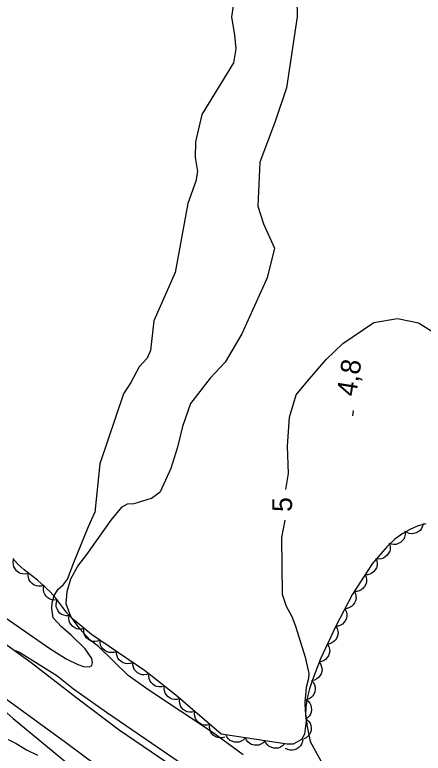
# Model space of a CAD drawing. Extents: x 282461 to 284471, y 5554090 to 5557646.
# Drawn here: x 283492.9 to 283555, y 5555063.9 to 5555176.2 of the extents above; entities that cross this region are included whole.
import ezdxf

# ---------------------------------------------------------------- set-up
doc = ezdxf.new("R2010")
doc.units = 0
for name, color, linetype in [('Niveau 1', 7, 'Continuous'), ('Niveau 2', 7, 'Continuous'), ('Niveau 21', 7, 'Continuous'), ('Niveau 3', 7, 'Continuous'), ('Niveau 44', 7, 'Continuous')]:
    doc.layers.add(name, color=color, linetype=linetype)

msp = doc.modelspace()

# ---------------------------------------------------------------- linework, layer by layer
at = {"layer": 'Niveau 1'}
for points in [[(283535.71, 5555181.58), (283535.78, 5555175.9), (283534.16, 5555165.1), (283532.47, 5555159.98), (283530.1, 5555153.8), (283529.83, 5555147.08), (283530.68, 5555144.42), (283532.35, 5555140.72), (283531.24, 5555136.19), (283527.39, 5555127.68), (283524.88, 5555123.37), (283522.58, 5555120.91), (283519.61, 5555117.05), (283518.37, 5555113.56), (283517.59, 5555110.42), (283516.58, 5555107.17), (283515, 5555103.66)], [(283534.05, 5555103.98), (283534.49, 5555106.41), (283534.33, 5555110.59), (283534.62, 5555115), (283535.63, 5555118.37), (283537.35, 5555120.48), (283540.22, 5555123.75), (283542.75, 5555126.21), (283547.47, 5555129.39), (283551.07, 5555130.01), (283554.22, 5555129.34), (283557.5, 5555127.29)], [(283527.58, 5555063.66), (283523.05, 5555067), (283513.09, 5555073.55), (283510.09, 5555075.7), (283505.62, 5555080.12), (283504.32, 5555081.1), (283502.78, 5555082.81), (283501.4, 5555084.7), (283500.69, 5555086.61), (283500.84, 5555088.48), (283501.38, 5555090.39), (283502.44, 5555092.31), (283503.84, 5555094.12), (283507.51, 5555099.31), (283509.19, 5555101.36), (283510.02, 5555101.82), (283511.03, 5555101.88), (283513.64, 5555102.66), (283515, 5555103.66)], [(283533.92, 5555099.32), (283533.44, 5555096.7), (283533.51, 5555088.08)], [(283533.51, 5555088.08), (283534.15, 5555086.27), (283534.99, 5555084.68), (283535.56, 5555083.19), (283537.02, 5555078.49), (283537.57, 5555075.99), (283537.51, 5555075.26), (283537.17, 5555073.86), (283536.95, 5555071.64), (283537.01, 5555070.29), (283537.31, 5555067.96), (283537.77, 5555065.66), (283539.94, 5555061.71)], [(283479.85, 5555080.49), (283480.04, 5555080), (283481.33, 5555078.62), (283485.67, 5555075.3), (283492.66, 5555069.16), (283500.75, 5555062.46), (283505.49, 5555059.03), (283506.31, 5555058.51), (283512.41, 5555053.82), (283513.23, 5555053.3), (283513.99, 5555052.67), (283517.16, 5555050.38), (283521.9, 5555047.01), (283527.52, 5555043.35), (283532.97, 5555039.58)], [(283550.97, 5555044.85), (283549.76, 5555044.49), (283548.78, 5555044.08), (283547.73, 5555044.13), (283546.28, 5555044.58), (283544.87, 5555045.26), (283541.66, 5555047.08), (283532.05, 5555053.31), (283527.43, 5555056.16), (283518.53, 5555062.05), (283506.82, 5555070.05), (283501.78, 5555073.6), (283499.26, 5555075.66), (283493.58, 5555079.2), (283493.03, 5555079.45)]]:
    msp.add_lwpolyline(points, dxfattribs=at)
at = {"layer": 'Niveau 2'}
for points in [[(283527.26, 5555199.65), (283526.63, 5555197.69), (283526.06, 5555191.79), (283525.15, 5555188.16), (283526.5, 5555180.27), (283525.83, 5555175.9), (283526.27, 5555173.11), (283526.46, 5555171.02), (283526.14, 5555168.87), (283521.3, 5555161.04), (283520.33, 5555156.89), (283520.28, 5555154.51), (283520.64, 5555152.38), (283520.4, 5555150.87), (283519.2, 5555147.47), (283517.27, 5555137.02), (283514.03, 5555129.65), (283513.53, 5555125.12), (283513, 5555123.99), (283511.76, 5555122.66), (283510.51, 5555120.28), (283509.4, 5555118.54), (283505.8, 5555107.91), (283505.07, 5555100.48)], [(283487.73, 5555087.06), (283498.22, 5555079.79), (283500.68, 5555078.25), (283502.44, 5555077.4), (283503.31, 5555077.06), (283504.24, 5555077.01), (283504.59, 5555077.24), (283504.7, 5555077.65), (283504.58, 5555078.29), (283503.57, 5555079.78), (283501.45, 5555081.85), (283499.99, 5555083.11), (283498.69, 5555084.49), (283498.5, 5555085.89), (283498.55, 5555086.76), (283498.88, 5555087.86), (283499.45, 5555088.85), (283500.26, 5555089.56), (283500.91, 5555090.36), (283501.86, 5555092.9), (283504.09, 5555098.34), (283505.07, 5555100.48)], [(283491.87, 5555065.98), (283493.1, 5555065.35), (283494.68, 5555064.38), (283496.32, 5555063.59)]]:
    msp.add_lwpolyline(points, dxfattribs=at)
at = {"layer": 'Niveau 21'}
for points in [[(283413.42, 5555140.21), (283421.33, 5555134.67), (283426.37, 5555130.54), (283431.1, 5555126.98), (283442.51, 5555117.98), (283465.73, 5555100.21), (283486.01, 5555084.44), (283495.36, 5555077.69), (283502.3, 5555072.3), (283508.75, 5555067.43), (283523.36, 5555057.48), (283536.74, 5555048.04), (283543.91, 5555042.83), (283565.1, 5555029.01), (283588.76, 5555014.39), (283602.76, 5555005.89), (283612.36, 5554999.72), (283619.33, 5554995.38), (283626, 5554991.56)], [(283425.48, 5555124.33), (283433.79, 5555117.1), (283443.38, 5555109.82), (283454.24, 5555101.15), (283463.77, 5555093.41), (283469.75, 5555088.42), (283480.65, 5555079.87), (283491.05, 5555072.49), (283500.6, 5555065.57), (283510.11, 5555058.47)]]:
    msp.add_lwpolyline(points, dxfattribs=at)
at = {"layer": 'Niveau 3'}
msp.add_line((283544.25, 5555115.2), (283544.37, 5555115.99), dxfattribs=at)
at = {"layer": 'Niveau 44'}
for points in [[(283554.94, 5555098.82), (283554.86, 5555098.41), (283554.67, 5555098.05), (283554.48, 5555097.78), (283554.2, 5555097.56), (283553.88, 5555097.38), (283553.51, 5555097.29), (283553.18, 5555097.25), (283552.84, 5555097.31), (283552.49, 5555097.43), (283552.18, 5555097.62)], [(283555.34, 5555098.76), (283554.17, 5555098.49), (283553, 5555097.98), (283551.84, 5555097.3), (283550.65, 5555096.43), (283549.46, 5555095.33), (283547.18, 5555092.68), (283544.21, 5555088.06), (283541.67, 5555083.21), (283539.34, 5555078.22), (283538.14, 5555075.06), (283537.67, 5555073.65), (283537.32, 5555072.27), (283537.09, 5555070.92), (283537.06, 5555069.65), (283537.19, 5555068.8), (283536.92, 5555066.78), (283536.47, 5555065.96), (283535.2, 5555065.26), (283534.27, 5555065.25), (283524.27, 5555066.78), (283517.34, 5555072.69), (283514.23, 5555075.22), (283512.61, 5555076.47), (283504.53, 5555081.95), (283501.9, 5555084.13), (283500.78, 5555085.24), (283499.14, 5555087.44), (283498.24, 5555088.44), (283496.34, 5555090.18), (283494.32, 5555091.77), (283493.42, 5555092.61), (283492.59, 5555093.49)], [(283552.2, 5555097.57), (283552.22, 5555097.15), (283552.12, 5555096.75), (283551.99, 5555096.45), (283551.77, 5555096.17), (283551.49, 5555095.93), (283551.15, 5555095.76), (283550.84, 5555095.65), (283550.49, 5555095.63), (283550.12, 5555095.67), (283549.78, 5555095.79)], [(283549.81, 5555095.74), (283549.92, 5555095.34), (283549.91, 5555094.93), (283549.86, 5555094.6), (283549.7, 5555094.29), (283549.49, 5555093.99), (283549.19, 5555093.74), (283548.92, 5555093.56), (283548.58, 5555093.46), (283548.21, 5555093.42), (283547.85, 5555093.46)], [(283494.9, 5555091.22), (283494.5, 5555091.13), (283494.09, 5555091.16), (283493.77, 5555091.23), (283493.46, 5555091.39), (283493.16, 5555091.62), (283492.93, 5555091.93), (283492.76, 5555092.21), (283492.68, 5555092.55), (283492.65, 5555092.92), (283492.71, 5555093.28)], [(283547.74, 5555093.55), (283547.9, 5555093.16), (283547.95, 5555092.76), (283547.94, 5555092.43), (283547.83, 5555092.09), (283547.66, 5555091.77), (283547.4, 5555091.48), (283547.16, 5555091.27), (283546.83, 5555091.12), (283546.47, 5555091.03), (283546.11, 5555091.02)], [(283497.31, 5555089.42), (283496.91, 5555089.29), (283496.5, 5555089.28), (283496.17, 5555089.32), (283495.85, 5555089.46), (283495.54, 5555089.67), (283495.28, 5555089.95), (283495.09, 5555090.21), (283494.98, 5555090.55), (283494.92, 5555090.92), (283494.95, 5555091.28)], [(283546.11, 5555091.02), (283546.28, 5555090.64), (283546.32, 5555090.23), (283546.31, 5555089.9), (283546.21, 5555089.57), (283546.03, 5555089.24), (283545.78, 5555088.95), (283545.53, 5555088.74), (283545.21, 5555088.6), (283544.85, 5555088.5), (283544.49, 5555088.49)], [(283499.35, 5555087.21), (283498.94, 5555087.15), (283498.53, 5555087.21), (283498.22, 5555087.31), (283497.92, 5555087.5), (283497.65, 5555087.75), (283497.45, 5555088.08), (283497.3, 5555088.37), (283497.25, 5555088.72), (283497.25, 5555089.09), (283497.34, 5555089.44)], [(283544.45, 5555088.52), (283544.65, 5555088.15), (283544.73, 5555087.75), (283544.75, 5555087.42), (283544.67, 5555087.08), (283544.53, 5555086.73), (283544.3, 5555086.43), (283544.07, 5555086.19), (283543.76, 5555086.02), (283543.41, 5555085.9), (283543.06, 5555085.85)], [(283501.12, 5555084.78), (283500.71, 5555084.76), (283500.31, 5555084.86), (283500, 5555084.98), (283499.73, 5555085.2), (283499.48, 5555085.48), (283499.31, 5555085.82), (283499.19, 5555086.13), (283499.17, 5555086.48), (283499.21, 5555086.85), (283499.33, 5555087.19)], [(283543.06, 5555085.85), (283543.25, 5555085.49), (283543.33, 5555085.09), (283543.36, 5555084.76), (283543.28, 5555084.41), (283543.13, 5555084.07), (283542.9, 5555083.77), (283542.68, 5555083.53), (283542.37, 5555083.36), (283542.02, 5555083.23), (283541.66, 5555083.19)], [(283503.44, 5555082.85), (283503.04, 5555082.73), (283502.63, 5555082.74), (283502.31, 5555082.79), (283501.99, 5555082.93), (283501.68, 5555083.14), (283501.43, 5555083.44), (283501.25, 5555083.7), (283501.14, 5555084.04), (283501.09, 5555084.41), (283501.13, 5555084.77)], [(283541.66, 5555083.19), (283541.88, 5555082.83), (283541.98, 5555082.44), (283542.01, 5555082.11), (283541.95, 5555081.76), (283541.82, 5555081.42), (283541.6, 5555081.1), (283541.39, 5555080.85), (283541.09, 5555080.67), (283540.75, 5555080.53), (283540.39, 5555080.47)], [(283505.85, 5555081.06), (283505.46, 5555080.9), (283505.05, 5555080.87), (283504.72, 5555080.88), (283504.39, 5555081), (283504.07, 5555081.18), (283503.79, 5555081.44), (283503.58, 5555081.69), (283503.44, 5555082.02), (283503.36, 5555082.38), (283503.36, 5555082.74)], [(283508.33, 5555079.37), (283507.95, 5555079.21), (283507.54, 5555079.18), (283507.21, 5555079.2), (283506.88, 5555079.31), (283506.55, 5555079.49), (283506.28, 5555079.76), (283506.07, 5555080.01), (283505.93, 5555080.33), (283505.85, 5555080.7), (283505.85, 5555081.06)], [(283540.39, 5555080.47), (283540.61, 5555080.11), (283540.7, 5555079.72), (283540.74, 5555079.39), (283540.68, 5555079.04), (283540.55, 5555078.69), (283540.33, 5555078.38), (283540.12, 5555078.13), (283539.82, 5555077.95), (283539.48, 5555077.81), (283539.12, 5555077.75)], [(283510.82, 5555077.68), (283510.43, 5555077.53), (283510.03, 5555077.49), (283509.7, 5555077.51), (283509.36, 5555077.63), (283509.04, 5555077.81), (283508.76, 5555078.07), (283508.55, 5555078.32), (283508.42, 5555078.65), (283508.33, 5555079.01), (283508.33, 5555079.37)], [(283513.31, 5555076), (283512.92, 5555075.84), (283512.51, 5555075.81), (283512.18, 5555075.82), (283511.85, 5555075.94), (283511.53, 5555076.12), (283511.25, 5555076.39), (283511.04, 5555076.63), (283510.9, 5555076.96), (283510.82, 5555077.32), (283510.82, 5555077.68)], [(283539.16, 5555077.73), (283539.4, 5555077.39), (283539.52, 5555077), (283539.58, 5555076.68), (283539.55, 5555076.33), (283539.45, 5555075.97), (283539.25, 5555075.64), (283539.06, 5555075.38), (283538.77, 5555075.17), (283538.44, 5555075.01), (283538.09, 5555074.92)], [(283515.63, 5555074.08), (283515.23, 5555073.96), (283514.82, 5555073.96), (283514.49, 5555074.01), (283514.17, 5555074.15), (283513.86, 5555074.36), (283513.61, 5555074.65), (283513.42, 5555074.92), (283513.32, 5555075.25), (283513.27, 5555075.62), (283513.3, 5555075.98)], [(283517.96, 5555072.19), (283517.56, 5555072.07), (283517.15, 5555072.07), (283516.82, 5555072.11), (283516.5, 5555072.26), (283516.2, 5555072.46), (283515.94, 5555072.75), (283515.75, 5555073.02), (283515.65, 5555073.36), (283515.6, 5555073.72), (283515.63, 5555074.08)], [(283538, 5555074.95), (283538.28, 5555074.64), (283538.45, 5555074.27), (283538.55, 5555073.95), (283538.55, 5555073.6), (283538.49, 5555073.23), (283538.34, 5555072.88), (283538.17, 5555072.6), (283537.91, 5555072.36), (283537.6, 5555072.16), (283537.26, 5555072.04)], [(283520.23, 5555070.22), (283519.83, 5555070.11), (283519.42, 5555070.12), (283519.1, 5555070.17), (283518.78, 5555070.33), (283518.48, 5555070.54), (283518.23, 5555070.84), (283518.05, 5555071.11), (283517.95, 5555071.45), (283517.91, 5555071.81), (283517.95, 5555072.17)], [(283537.12, 5555072.05), (283537.46, 5555071.81), (283537.71, 5555071.48), (283537.87, 5555071.2), (283537.95, 5555070.86), (283537.98, 5555070.49), (283537.9, 5555070.11), (283537.81, 5555069.8), (283537.61, 5555069.51), (283537.35, 5555069.24), (283537.05, 5555069.05)], [(283522.52, 5555068.27), (283522.12, 5555068.16), (283521.71, 5555068.17), (283521.38, 5555068.22), (283521.06, 5555068.38), (283520.76, 5555068.59), (283520.52, 5555068.89), (283520.33, 5555069.16), (283520.24, 5555069.5), (283520.19, 5555069.87), (283520.23, 5555070.22)], [(283537.22, 5555069.05), (283537.54, 5555068.77), (283537.75, 5555068.43), (283537.88, 5555068.12), (283537.93, 5555067.78), (283537.91, 5555067.41), (283537.8, 5555067.04), (283537.67, 5555066.74), (283537.43, 5555066.47), (283537.15, 5555066.24), (283536.83, 5555066.08)], [(283524.8, 5555066.32), (283524.4, 5555066.21), (283523.99, 5555066.22), (283523.67, 5555066.28), (283523.35, 5555066.43), (283523.05, 5555066.64), (283522.8, 5555066.94), (283522.62, 5555067.21), (283522.52, 5555067.55), (283522.48, 5555067.92), (283522.52, 5555068.27)], [(283527.93, 5555066.22), (283527.65, 5555065.91), (283527.3, 5555065.71), (283526.99, 5555065.58), (283526.64, 5555065.54), (283526.27, 5555065.57), (283525.91, 5555065.69), (283525.61, 5555065.82), (283525.35, 5555066.06), (283525.12, 5555066.35), (283524.96, 5555066.67)], [(283530.9, 5555065.76), (283530.62, 5555065.46), (283530.27, 5555065.25), (283529.96, 5555065.12), (283529.61, 5555065.09), (283529.24, 5555065.11), (283528.88, 5555065.23), (283528.58, 5555065.37), (283528.32, 5555065.6), (283528.09, 5555065.89), (283527.93, 5555066.22)], [(283533.87, 5555065.31), (283533.59, 5555065), (283533.24, 5555064.8), (283532.93, 5555064.67), (283532.58, 5555064.63), (283532.21, 5555064.66), (283531.85, 5555064.78), (283531.55, 5555064.91), (283531.29, 5555065.15), (283531.06, 5555065.44), (283530.9, 5555065.76)], [(283536.67, 5555066.07), (283536.63, 5555065.65), (283536.47, 5555065.27), (283536.31, 5555064.99), (283536.06, 5555064.74), (283535.75, 5555064.54), (283535.39, 5555064.41), (283535.07, 5555064.34), (283534.72, 5555064.36), (283534.36, 5555064.45), (283534.04, 5555064.62)]]:
    msp.add_lwpolyline(points, dxfattribs=at)

# ---------------------------------------------------------------- texts
at = {"layer": 'Niveau 1'}
msp.add_text('5', height=3, rotation=90.0669, dxfattribs=at).set_placement((283535.02, 5555100.59))
at = {"layer": 'Niveau 3'}
msp.add_text('4,8  ', height=3, rotation=81.0957, dxfattribs=at).set_placement((283544.73, 5555118.04))

doc.saveas('drawing.dxf')
